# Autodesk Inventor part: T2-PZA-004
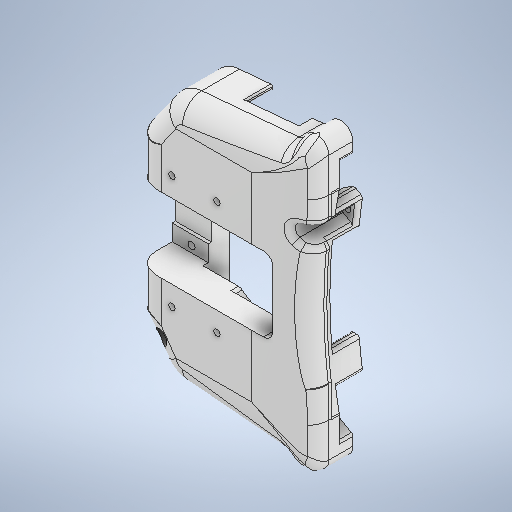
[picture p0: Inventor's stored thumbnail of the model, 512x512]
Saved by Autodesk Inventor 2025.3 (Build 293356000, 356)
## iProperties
Created: 2026-10
Part Number: T2-PZA-004
Material: Genérico
Description: Placa superior del gripper
Document SubType Name: Modeling
Designer: Luis MuÃ±oz
Density: 1 g/cm^3
Appearance: Valor por defecto
Project: TESIS 2 - Plataforma mecatrÃ³nica preventiva desacoplada
Sending System: ONSHAPE BY PTC INC, 1.194
Preprocessor: ST-DEVELOPER v20
Material_Fabricacion: PLA
Title: Placa superior del gripper
Revision Number: 00
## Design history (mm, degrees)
feature "Top_Plate"
sketch "Boceto1"
  geometry: L1 (9, 37.937)-(9, 50.699) reference; L2 (0, 0)-(0, 51.054) reference; L3 (0, 0)-(11.5, 0) reference; L4 (11.5, 0)-(11.5, 13.117) reference; L5 (11.5, 13.117)-(7.2, 13.117) reference; L6 (7.2, 13.117)-(7.2, 18.527) reference; L7 (7.2, 18.527)-(6.1, 18.527) reference; L8 (6.1, 32.527)-(6.1, 18.527) reference; L9 (7.2, 32.527)-(6.1, 32.527) reference; L10 (7.2, 32.527)-(7.2, 37.937) reference; L11 (11.5, 37.937)-(7.2, 37.937) reference; L12 (11.5, 37.937)-(11.5, 51.054) reference; L13 (11.5, 51.054)-(0, 51.054) reference; C1 r 1.25 at (5.6, 3.527) reference; C2 r 1.25 at (5.6, 47.527) reference; C3 r 1.25 at (3, 36.527) reference; C4 r 1.25 at (3, 14.527) reference; 1 further point
extrude "Extrusión1" join sketch "Boceto1" stored distance "d0" = 10; taper "d1" = 0 deg
sketch "Boceto2"
  geometry: L1 (9, 9.344)-(0, 9.344) reference; L2 (0, 0)-(0, 51.054) reference; L3 (0, 0)-(11.5, 0) reference; L4 (11.5, 0)-(11.5, 13.117) reference; L5 (11.5, 13.117)-(7.2, 13.117) reference; L6 (7.2, 13.117)-(7.2, 18.527) reference; L7 (7.2, 18.527)-(6.1, 18.527) reference; L8 (6.1, 32.527)-(6.1, 18.527) reference; L9 (7.2, 32.527)-(6.1, 32.527) reference; L10 (7.2, 32.527)-(7.2, 37.937) reference; L11 (11.5, 37.937)-(7.2, 37.937) reference; L12 (11.5, 37.937)-(11.5, 51.054) reference; L13 (11.5, 51.054)-(0, 51.054) reference; C1 r 1.25 at (5.6, 3.527) reference; C2 r 1.25 at (5.6, 47.527) reference; C3 r 1.25 at (5.6, 47.527); C4 r 1.25 at (5.6, 47.527) reference; C5 r 2 at (5.6, 47.527); C6 r 2 at (5.6, 3.527); 1 further point
  constraints: 3 centre point, 3 coincident, 1 concentric
  dimensions: "d2" = 4 diameter of C5; "d3" = 4 diameter of C6
extrude "Extrusión2" cut sketch "Boceto2" distance "d4" = 8; taper "d5" = 0 deg
sketch "Boceto3"
  geometry: L1 (-7.828, -11.653)-(-0.271, -0.86) reference; L2 (0, 0)-(0, 51.054) reference; L3 (-7.828, 62.707)-(-0.271, 51.914) reference; L4 (-25.608, 67.849)-(-15.148, 66.933) reference; L5 (-26.194, 66.896)-(-26.15, 67.394) reference; L6 (-15.279, 65.439)-(-25.739, 66.354) reference; L7 (-11.346, 61.181)-(-14, 58.527) reference; L8 (-12.586, 52.113)-(-14, 53.527) reference; L9 (-12, 0.355)-(-12, 50.699) reference; L10 (-12.586, -1.059)-(-14, -2.473) reference; L11 (-11.346, -10.127)-(-14, -7.473) reference; L12 (-15.279, -14.385)-(-25.739, -15.3) reference; L13 (-26.194, -15.842)-(-26.15, -16.34) reference; L14 (-25.608, -16.794)-(-15.148, -15.879) reference; C1 r 2.5 at (-6.446, 35.777) reference; C2 r 2.5 at (-6.446, 15.277) reference; C3 r 1.4 at (-8, -4.473) reference; C4 r 1.025 at (-8, 55.527) reference; A1 r 1.5 centre (-1.5, 0) between (-0.271, -0.86) and (0, 0) reference; A2 r 1.5 centre (-1.5, 51.054) between (0, 51.054) and (-0.271, 51.914) reference; A3 r 10 centre (-16.02, 56.972) between (-7.828, 62.707) and (-15.148, 66.933) reference; A4 r 0.5 centre (-25.652, 67.351) between (-25.608, 67.849) and (-26.15, 67.394) reference; A5 r 0.5 centre (-25.696, 66.852) between (-26.194, 66.896) and (-25.739, 66.354) reference; A6 r 8.5 centre (-16.02, 56.972) between (-11.757, 64.325) and (-15.279, 65.439) reference; A7 r 2 centre (-12.76, 62.595) between (-11.346, 61.181) and (-11.757, 64.325) reference; A8 r 3.536 centre (-11.5, 56.027) between (-14, 58.527) and (-14, 53.527) reference; A9 r 2 centre (-14, 50.699) between (-12, 50.699) and (-12.586, 52.113) reference; A10 r 2 centre (-14, 0.355) between (-12.586, -1.059) and (-12, 0.355) reference; A11 r 3.536 centre (-11.5, -4.973) between (-14, -2.473) and (-14, -7.473) reference; A12 r 2 centre (-12.76, -11.541) between (-11.757, -13.271) and (-11.346, -10.127) reference; A13 r 8.5 centre (-16.02, -5.917) between (-15.279, -14.385) and (-11.757, -13.271) reference; A14 r 0.5 centre (-25.696, -15.798) between (-25.739, -15.3) and (-26.194, -15.842) reference; A15 r 0.5 centre (-25.652, -16.296) between (-26.15, -16.34) and (-25.608, -16.794) reference; A16 r 10 centre (-16.02, -5.917) between (-15.148, -15.879) and (-7.828, -11.653) reference; 1 further point
extrude "Extrusión3" cut sketch "Boceto3" stored distance "d6" = 10; taper "d7" = 0 deg
node "Sólido1"
node "Contorno proyectado1"
node "Contorno proyectado2"
node "Contorno proyectado3"
